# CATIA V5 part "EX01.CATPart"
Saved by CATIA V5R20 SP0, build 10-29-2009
Part number: EX1
Bounding box of the stored display mesh (mm): x -50 to 0, y 0 to 50, z 0 to 10
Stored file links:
  E:\Nouveau dossier\tarek\mécaniquee\Catia\TP 0\EX01.CATPart
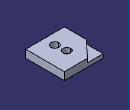
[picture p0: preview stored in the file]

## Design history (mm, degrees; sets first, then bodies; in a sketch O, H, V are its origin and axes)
Set1
  DatumSurface1 to DatumSurface12
Body1 (main body)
